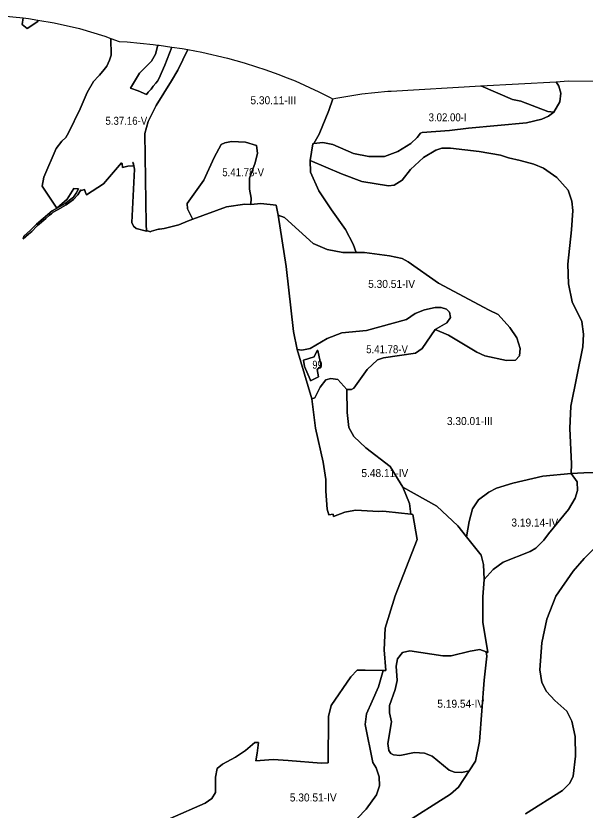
# Model space of a CAD drawing. Extents: x -591496 to -585489, y -1120610 to -1115685.
# Drawn here: x -589052 to -587628, y -1117681 to -1115696 of the extents above; entities that cross this region are included whole.
import ezdxf

# ---------------------------------------------------------------- set-up
doc = ezdxf.new("R2010")
doc.units = 0
doc.header["$LTSCALE"] = 8
doc.layers.add('40', color=7, linetype='Continuous', lineweight=25)
doc.layers.add('41', color=7, linetype='Continuous')

msp = doc.modelspace()

# ---------------------------------------------------------------- linework, layer by layer
at = {"layer": '40'}
for points in [[(-589085.427, -1115695.631), (-589033.025, -1115700.792), (-589035.5, -1115717.5), (-589023, -1115727.5), (-588997, -1115710), (-588996.427, -1115705.987), (-588955.74, -1115712.705), (-588892.011, -1115727.564), (-588829.39, -1115746.56), (-588813.95, -1115752.131), (-588813.5, -1115793.5), (-588817, -1115806), (-588823.97, -1115821.682), (-588830.41, -1115829.51), (-588842.09, -1115843.72), (-588844.5, -1115846.5), (-588857.5, -1115860), (-588873, -1115887), (-588890.503, -1115927.983), (-588920.25, -1115987.71), (-588926.285, -1115999.825), (-588926.5, -1116000), (-588937, -1116009), (-588950.5, -1116027), (-588982, -1116099), (-588985.5, -1116121.5), (-588949.5, -1116176), (-588923.5, -1116154), (-588906.817, -1116126.89), (-588894.56, -1116128.32), (-588900.38, -1116138.54), (-588907.74, -1116148.78), (-588910.49, -1116151.61), (-588928.5, -1116164.37), (-588941.5, -1116171.98), (-588960.88, -1116183.34), (-589000.12, -1116216.23), (-589015, -1116231.4), (-589031.8, -1116246.22), (-589032.98, -1116252.79), (-589020.34, -1116241.61), (-589012.05, -1116234.28), (-588999.48, -1116221.09), (-588997.78, -1116219.31), (-588976.73, -1116201.93), (-588967.37, -1116194.2), (-588962.57, -1116190.24), (-588959.07, -1116187.36), (-588958.15, -1116186.6), (-588938.64, -1116175.23), (-588937.13, -1116174.34), (-588925.78, -1116167.73), (-588907.39, -1116154.39), (-588896.85, -1116143.36), (-588891.47, -1116135), (-588888.661, -1116130.174), (-588887, -1116132.5), (-588880.305, -1116129.896), (-588877.56, -1116137.13), (-588875.1, -1116143.13), (-588832.19, -1116115.72), (-588787.477, -1116063.178), (-588786, -1116064.5), (-588785.405, -1116064.294), (-588784.46, -1116074.54), (-588771.67, -1116071.57), (-588756.88, -1116070.64), (-588758.78, -1116062.47), (-588758.357, -1116062.372), (-588754.5, -1116078.5), (-588761.5, -1116212.5), (-588757.5, -1116221.5), (-588751, -1116227), (-588725, -1116233.5), (-588721.219, -1116232.878), (-588715.72, -1116235.81), (-588712.16, -1116234.05), (-588700.61, -1116230.81), (-588694.53, -1116229.1), (-588692.58, -1116228.81), (-588680.32, -1116226.82), (-588643.83, -1116218.02), (-588622.31, -1116208.8), (-588609.21, -1116204.06), (-588524.463, -1116173.401), (-588479, -1116166.5), (-588464, -1116167), (-588438.5, -1116165), (-588400, -1116168.5), (-588395, -1116194), (-588375.5, -1116322.5), (-588357, -1116484.5), (-588348, -1116529.5), (-588311, -1116653), (-588302, -1116726), (-588283, -1116811.5), (-588276.5, -1116855), (-588276.5, -1116883.5)], [(-587579.5, -1116836.5), (-587630.5, -1116838), (-587662.5, -1116840), (-587662, -1116815.5), (-587665.5, -1116727), (-587663, -1116671.5), (-587633.5, -1116523), (-587631.5, -1116491.5), (-587636, -1116460), (-587660, -1116410.5), (-587669, -1116365.5), (-587670.5, -1116316), (-587662, -1116230.5), (-587658, -1116182.5), (-587660.5, -1116158.5), (-587670, -1116131.5), (-587698, -1116100), (-587732, -1116076.5), (-587755.5, -1116066), (-587790, -1116057.5), (-587819, -1116050.5), (-587839, -1116044), (-587892.5, -1116035), (-587964, -1116026), (-587986, -1116026), (-588001, -1116031.5), (-588032, -1116050), (-588064, -1116080), (-588085, -1116106), (-588105, -1116119), (-588119, -1116120.5), (-588186, -1116110), (-588237, -1116090.5), (-588315, -1116057.5), (-588308.5, -1116015.5), (-588306, -1116015), (-588283.5, -1116012), (-588258.5, -1116017), (-588207, -1116039.5), (-588168.5, -1116047.5), (-588129.5, -1116047.5), (-588096, -1116034.5), (-588063.5, -1116015), (-588047.5, -1116000), (-588039.5, -1115989), (-588035, -1115987.5), (-587967, -1115982.5), (-587919, -1115976.5), (-587774.5, -1115963), (-587736, -1115954), (-587719.5, -1115946.5), (-587705.5, -1115936.5), (-587691, -1115910.5), (-587688.5, -1115888.5), (-587693, -1115871.5), (-587699.742, -1115860.123), (-587669.707, -1115858.407), (-587547.277, -1115858.921)], [(-588085, -1117718), (-587964.5, -1117641.5), (-587944.5, -1117623.5), (-587918, -1117583), (-587902, -1117559), (-587892, -1117509.5), (-587880, -1117356.5), (-587873.5, -1117296.5), (-587875, -1117285.5), (-587871, -1117287), (-587883.5, -1117211), (-587883.5, -1117148), (-587880, -1117104.5), (-587857.5, -1117080), (-587832.5, -1117061), (-587765, -1117034.5), (-587751, -1117026), (-587730.5, -1117006), (-587719, -1116990.5), (-587669.5, -1116930), (-587652, -1116901), (-587646.5, -1116882), (-587647, -1116860.5), (-587662.5, -1116840), (-587630.5, -1116838), (-587579.5, -1116836.5)], [(-588276.5, -1116883.5), (-588273, -1116928.5), (-588269, -1116943), (-588257.783, -1116941.026), (-588257.78, -1116941.07), (-588257.29, -1116946.81), (-588228.999, -1116935.96), (-588206.5, -1116932), (-588200.967, -1116931.385), (-588144.53, -1116934.48), (-588134.232, -1116933.846), (-588125, -1116934.5), (-588063.5, -1116941), (-588061.589, -1116941.212), (-588058.91, -1116941.996), (-588047.5, -1117005), (-588102.5, -1117145.5), (-588127.5, -1117226.5), (-588130.5, -1117280.5), (-588126, -1117332.5), (-588132.5, -1117332.5), (-588177.5, -1117331), (-588197.5, -1117331), (-588214, -1117348), (-588262.5, -1117420), (-588269.5, -1117447), (-588270.5, -1117563), (-588288, -1117564), (-588370, -1117557.5), (-588407.5, -1117555), (-588451.5, -1117558), (-588448, -1117538.5), (-588445, -1117512.5), (-588454, -1117512), (-588477.5, -1117532.5), (-588502, -1117549), (-588535, -1117566), (-588548, -1117577), (-588552, -1117598.5), (-588552.5, -1117637.5), (-588561, -1117652.5), (-588578, -1117664), (-588666, -1117702.5)], [(-588218.5, -1117724), (-588175.5, -1117679), (-588149, -1117643), (-588142, -1117620.5), (-588142.5, -1117598), (-588150.5, -1117575.5), (-588159, -1117562), (-588178, -1117467.5), (-588174.5, -1117440.5), (-588160, -1117409), (-588144, -1117373), (-588132.5, -1117332.5), (-588126, -1117332.5), (-588130.5, -1117280.5), (-588127.5, -1117226.5), (-588102.5, -1117145.5), (-588047.5, -1117005), (-588058.91, -1116941.996), (-588061.589, -1116941.212), (-588063.5, -1116941), (-588066.5, -1116914.5), (-588083.5, -1116873.5), (-587998.5, -1116921), (-587946, -1116970.5), (-587924, -1116998)], [(-587777, -1117690.5), (-587684.5, -1117632), (-587666, -1117614), (-587657.5, -1117596), (-587651.5, -1117546.5), (-587652.5, -1117497), (-587660.5, -1117459), (-587673.5, -1117434), (-587703, -1117407), (-587724, -1117384.5), (-587735.5, -1117362), (-587740.5, -1117330.5), (-587735.5, -1117263), (-587723.5, -1117204), (-587701, -1117146), (-587657.5, -1117083.5), (-587629.5, -1117052.5), (-587552, -1116975.5)], [(-587552, -1116975.5), (-587629.5, -1117052.5), (-587657.5, -1117083.5), (-587701, -1117146), (-587723.5, -1117204), (-587735.5, -1117263), (-587740.5, -1117330.5), (-587735.5, -1117362), (-587724, -1117384.5), (-587703, -1117407), (-587673.5, -1117434), (-587660.5, -1117459), (-587652.5, -1117497), (-587651.5, -1117546.5), (-587657.5, -1117596), (-587666, -1117614), (-587684.5, -1117632), (-587777, -1117690.5)], [(-587924, -1116998), (-587887.5, -1117044), (-587881.5, -1117067), (-587880, -1117104.5), (-587883.5, -1117148), (-587883.5, -1117211), (-587871, -1117287), (-587875, -1117285.5), (-587891, -1117279.5), (-587915, -1117283.5), (-587962.5, -1117295.5), (-587983.5, -1117295.5), (-588066, -1117283), (-588084.5, -1117287.5), (-588097, -1117303), (-588100, -1117321), (-588098, -1117357), (-588103, -1117379.5), (-588117, -1117420), (-588116.5, -1117438), (-588111.5, -1117460.5), (-588121, -1117514.5), (-588118.5, -1117532.5), (-588113.5, -1117539.5), (-588107, -1117543), (-588091, -1117544.5), (-588054, -1117537), (-588029, -1117539), (-588010, -1117546.5), (-587968, -1117581), (-587954.5, -1117586.5), (-587936, -1117587.5), (-587918, -1117583), (-587944.5, -1117623.5), (-587964.5, -1117641.5), (-588085, -1117718)], [(-588666, -1117702.5), (-588578, -1117664), (-588561, -1117652.5), (-588552.5, -1117637.5), (-588552, -1117598.5), (-588548, -1117577), (-588535, -1117566), (-588502, -1117549), (-588477.5, -1117532.5), (-588454, -1117512), (-588445, -1117512.5), (-588448, -1117538.5), (-588451.5, -1117558), (-588407.5, -1117555), (-588370, -1117557.5), (-588288, -1117564), (-588270.5, -1117563), (-588269.5, -1117447), (-588262.5, -1117420), (-588214, -1117348), (-588197.5, -1117331), (-588177.5, -1117331), (-588132.5, -1117332.5), (-588144, -1117373), (-588160, -1117409), (-588174.5, -1117440.5), (-588178, -1117467.5), (-588159, -1117562), (-588150.5, -1117575.5), (-588142.5, -1117598), (-588142, -1117620.5), (-588149, -1117643), (-588175.5, -1117679), (-588218.5, -1117724)]]:
    msp.add_lwpolyline(points, dxfattribs=at)
for points in [[(-588997, -1115710), (-589023, -1115727.5), (-589035.5, -1115717.5), (-589033.025, -1115700.792), (-589020.304, -1115702.045), (-588996.427, -1115705.987)], [(-588745.52, -1115883.13), (-588724.53, -1115891.88), (-588720.22, -1115886.6), (-588713.53, -1115878.72), (-588707.84, -1115871.45), (-588701.53, -1115863.78), (-588697.583, -1115859.19), (-588693.731, -1115853.252), (-588678.873, -1115819.155), (-588661.07, -1115773.804), (-588635.894, -1115777.499), (-588621.728, -1115779.945), (-588646, -1115831), (-588662.5, -1115858), (-588701, -1115920), (-588721, -1115959.5), (-588729, -1115989.5), (-588725.5, -1116216), (-588725, -1116233.5), (-588751, -1116227), (-588757.5, -1116221.5), (-588761.5, -1116212.5), (-588754.5, -1116078.5), (-588758.357, -1116062.372), (-588758.78, -1116062.47), (-588756.88, -1116070.64), (-588771.67, -1116071.57), (-588784.46, -1116074.54), (-588785.405, -1116064.294), (-588786, -1116064.5), (-588787.477, -1116063.178), (-588832.19, -1116115.72), (-588875.1, -1116143.13), (-588877.56, -1116137.13), (-588880.305, -1116129.896), (-588887, -1116132.5), (-588888.661, -1116130.174), (-588891.47, -1116135), (-588896.85, -1116143.36), (-588907.39, -1116154.39), (-588925.78, -1116167.73), (-588937.13, -1116174.34), (-588938.64, -1116175.23), (-588958.15, -1116186.6), (-588959.07, -1116187.36), (-588962.57, -1116190.24), (-588967.37, -1116194.2), (-588976.73, -1116201.93), (-588997.78, -1116219.31), (-588999.48, -1116221.09), (-589012.05, -1116234.28), (-589020.34, -1116241.61), (-589032.98, -1116252.79), (-589031.8, -1116246.22), (-589015, -1116231.4), (-589000.12, -1116216.23), (-588960.88, -1116183.34), (-588941.5, -1116171.98), (-588928.5, -1116164.37), (-588910.49, -1116151.61), (-588907.74, -1116148.78), (-588900.38, -1116138.54), (-588894.56, -1116128.32), (-588906.817, -1116126.89), (-588923.5, -1116154), (-588949.5, -1116176), (-588985.5, -1116121.5), (-588982, -1116099), (-588950.5, -1116027), (-588937, -1116009), (-588926.5, -1116000), (-588926.285, -1115999.825), (-588920.25, -1115987.71), (-588890.503, -1115927.983), (-588873, -1115887), (-588857.5, -1115860), (-588844.5, -1115846.5), (-588842.09, -1115843.72), (-588830.41, -1115829.51), (-588823.97, -1115821.682), (-588817, -1115806), (-588813.5, -1115793.5), (-588813.95, -1115752.131), (-588793.58, -1115759.481), (-588773.137, -1115760.611), (-588708.014, -1115767.025), (-588696.61, -1115768.612), (-588702, -1115791), (-588712, -1115809), (-588742, -1115838.5), (-588764.428, -1115876.491)], [(-588720.22, -1115886.6), (-588724.53, -1115891.88), (-588745.52, -1115883.13), (-588764.428, -1115876.491), (-588742, -1115838.5), (-588712, -1115809), (-588702, -1115791), (-588696.61, -1115768.612), (-588693.334, -1115769.069), (-588661.07, -1115773.804), (-588678.873, -1115819.155), (-588693.731, -1115853.252), (-588697.583, -1115859.19), (-588701.53, -1115863.78), (-588707.84, -1115871.45), (-588713.53, -1115878.72)], [(-588258.512, -1115902.831), (-588269, -1115932), (-588292.5, -1115991), (-588306, -1116015), (-588308.5, -1116015.5), (-588315, -1116057.5), (-588314.5, -1116086), (-588293.5, -1116133), (-588262, -1116180.5), (-588227, -1116230), (-588208, -1116266), (-588200.5, -1116287), (-588233.5, -1116287.5), (-588273, -1116279.5), (-588308, -1116265), (-588379.5, -1116200), (-588395, -1116194), (-588400, -1116168.5), (-588438.5, -1116165), (-588464, -1116167), (-588463, -1116151), (-588467.5, -1116128.5), (-588467.5, -1116101.5), (-588453, -1116063), (-588447.5, -1116038.5), (-588449.5, -1116020), (-588477, -1116011), (-588512, -1116009.5), (-588529, -1116013), (-588538, -1116017), (-588555.5, -1116049.5), (-588581.5, -1116106), (-588623, -1116164.5), (-588622, -1116178), (-588610, -1116203), (-588609.981, -1116202.991), (-588609.21, -1116204.06), (-588622.31, -1116208.8), (-588643.83, -1116218.02), (-588680.32, -1116226.82), (-588692.58, -1116228.81), (-588694.53, -1116229.1), (-588700.61, -1116230.81), (-588712.16, -1116234.05), (-588715.72, -1116235.81), (-588721.219, -1116232.878), (-588725, -1116233.5), (-588725.5, -1116216), (-588729, -1115989.5), (-588721, -1115959.5), (-588701, -1115920), (-588662.5, -1115858), (-588646, -1115831), (-588621.728, -1115779.945), (-588586.01, -1115786.115), (-588522.281, -1115800.974), (-588480.632, -1115813.108), (-588449.682, -1115822.858), (-588428.711, -1115829.72), (-588393.583, -1115842.38), (-588379.303, -1115847.83), (-588353.187, -1115858.22), (-588293.581, -1115885.227), (-588265.44, -1115899.662), (-588259.225, -1115902.976)], [(-587705.5, -1115936.5), (-587719.5, -1115946.5), (-587736, -1115954), (-587774.5, -1115963), (-587919, -1115976.5), (-587967, -1115982.5), (-588035, -1115987.5), (-588039.5, -1115989), (-588047.5, -1116000), (-588063.5, -1116015), (-588096, -1116034.5), (-588129.5, -1116047.5), (-588168.5, -1116047.5), (-588207, -1116039.5), (-588258.5, -1116017), (-588283.5, -1116012), (-588306, -1116015), (-588292.5, -1115991), (-588269, -1115932), (-588258.512, -1115902.831), (-588251.05, -1115901.315), (-588186.486, -1115890.655), (-588121.363, -1115884.241), (-588112.987, -1115883.727), (-587888.26, -1115870.891), (-587809.5, -1115904.5), (-587788, -1115909), (-587721, -1115934.5)], [(-587691, -1115910.5), (-587705.5, -1115936.5), (-587721, -1115934.5), (-587788, -1115909), (-587809.5, -1115904.5), (-587888.26, -1115870.891), (-587699.742, -1115860.123), (-587693, -1115871.5), (-587688.5, -1115888.5)], [(-588464, -1116167), (-588479, -1116166.5), (-588524.463, -1116173.401), (-588609.21, -1116204.06), (-588609.981, -1116202.991), (-588610, -1116203), (-588622, -1116178), (-588623, -1116164.5), (-588581.5, -1116106), (-588555.5, -1116049.5), (-588538, -1116017), (-588529, -1116013), (-588512, -1116009.5), (-588477, -1116011), (-588449.5, -1116020), (-588447.5, -1116038.5), (-588453, -1116063), (-588467.5, -1116101.5), (-588467.5, -1116128.5), (-588463, -1116151)], [(-587662.5, -1116840), (-587733.5, -1116846), (-587808, -1116863.5), (-587849, -1116876.5), (-587868.5, -1116886), (-587894, -1116905.5), (-587909, -1116928), (-587918, -1116959.5), (-587924, -1116998), (-587946, -1116970.5), (-587998.5, -1116921), (-588083.5, -1116873.5), (-588097, -1116852), (-588115, -1116822.5), (-588176, -1116775.5), (-588206, -1116747.5), (-588218.5, -1116725), (-588222.5, -1116687), (-588224, -1116630), (-588212, -1116630), (-588206, -1116626), (-588173, -1116579.5), (-588146.5, -1116555.5), (-588131.5, -1116550.5), (-588052, -1116538.5), (-588035, -1116527.5), (-588002.5, -1116480), (-587969, -1116494), (-587898.5, -1116536.5), (-587878, -1116545.5), (-587824.5, -1116557.5), (-587802, -1116556.5), (-587792, -1116545.5), (-587790, -1116527.5), (-587798, -1116500.5), (-587815.5, -1116475), (-587845, -1116442.5), (-587867.5, -1116431), (-587994, -1116363.5), (-588070.5, -1116310.5), (-588085, -1116302.5), (-588116.5, -1116295.5), (-588179.5, -1116287), (-588200.5, -1116287), (-588208, -1116266), (-588227, -1116230), (-588262, -1116180.5), (-588293.5, -1116133), (-588314.5, -1116086), (-588315, -1116057.5), (-588237, -1116090.5), (-588186, -1116110), (-588119, -1116120.5), (-588105, -1116119), (-588085, -1116106), (-588064, -1116080), (-588032, -1116050), (-588001, -1116031.5), (-587986, -1116026), (-587964, -1116026), (-587892.5, -1116035), (-587839, -1116044), (-587819, -1116050.5), (-587790, -1116057.5), (-587755.5, -1116066), (-587732, -1116076.5), (-587698, -1116100), (-587670, -1116131.5), (-587660.5, -1116158.5), (-587658, -1116182.5), (-587662, -1116230.5), (-587670.5, -1116316), (-587669, -1116365.5), (-587660, -1116410.5), (-587636, -1116460), (-587631.5, -1116491.5), (-587633.5, -1116523), (-587663, -1116671.5), (-587665.5, -1116727), (-587662, -1116815.5)], [(-588200.5, -1116287), (-588179.5, -1116287), (-588116.5, -1116295.5), (-588085, -1116302.5), (-588070.5, -1116310.5), (-587994, -1116363.5), (-587867.5, -1116431), (-587845, -1116442.5), (-587815.5, -1116475), (-587798, -1116500.5), (-587790, -1116527.5), (-587792, -1116545.5), (-587802, -1116556.5), (-587824.5, -1116557.5), (-587878, -1116545.5), (-587898.5, -1116536.5), (-587969, -1116494), (-588002.5, -1116480), (-587973.5, -1116463), (-587964, -1116449.5), (-587966.5, -1116436.5), (-587974, -1116429), (-587988, -1116425), (-588002.5, -1116425), (-588029.5, -1116430.5), (-588052.5, -1116439.5), (-588074, -1116455), (-588174.5, -1116482), (-588236, -1116488), (-588273, -1116502), (-588315, -1116527), (-588336, -1116531), (-588348, -1116529.5), (-588357, -1116484.5), (-588375.5, -1116322.5), (-588395, -1116194), (-588379.5, -1116200), (-588308, -1116265), (-588273, -1116279.5), (-588233.5, -1116287.5)], [(-588002.5, -1116480), (-588035, -1116527.5), (-588052, -1116538.5), (-588131.5, -1116550.5), (-588146.5, -1116555.5), (-588173, -1116579.5), (-588206, -1116626), (-588212, -1116630), (-588224, -1116630), (-588246, -1116605), (-588264, -1116602.5), (-588276.5, -1116605.5), (-588290.5, -1116624), (-588303.5, -1116650.5), (-588311, -1116653), (-588348, -1116529.5), (-588336, -1116531), (-588315, -1116527), (-588273, -1116502), (-588236, -1116488), (-588174.5, -1116482), (-588074, -1116455), (-588052.5, -1116439.5), (-588029.5, -1116430.5), (-588002.5, -1116425), (-587988, -1116425), (-587974, -1116429), (-587966.5, -1116436.5), (-587964, -1116449.5), (-587973.5, -1116463)], [(-588294.5, -1116598), (-588314.279, -1116607.889), (-588315.63, -1116604.29), (-588329.15, -1116572.2), (-588331.762, -1116556.451), (-588305, -1116548), (-588297.884, -1116531.989), (-588297.1, -1116531.88), (-588296.554, -1116532.031), (-588288, -1116571), (-588298, -1116580)], [(-588294.5, -1116598), (-588298, -1116580), (-588288, -1116571), (-588296.554, -1116532.031), (-588297.1, -1116531.88), (-588297.884, -1116531.989), (-588305, -1116548), (-588331.762, -1116556.451), (-588329.15, -1116572.2), (-588315.63, -1116604.29), (-588314.279, -1116607.889)], [(-588224, -1116630), (-588222.5, -1116687), (-588218.5, -1116725), (-588206, -1116747.5), (-588176, -1116775.5), (-588115, -1116822.5), (-588097, -1116852), (-588083.5, -1116873.5), (-588066.5, -1116914.5), (-588063.5, -1116941), (-588125, -1116934.5), (-588134.232, -1116933.846), (-588144.53, -1116934.48), (-588200.967, -1116931.385), (-588206.5, -1116932), (-588228.999, -1116935.96), (-588257.29, -1116946.81), (-588257.78, -1116941.07), (-588257.783, -1116941.026), (-588269, -1116943), (-588273, -1116928.5), (-588276.5, -1116883.5), (-588276.5, -1116855), (-588283, -1116811.5), (-588302, -1116726), (-588311, -1116653), (-588303.5, -1116650.5), (-588290.5, -1116624), (-588276.5, -1116605.5), (-588264, -1116602.5), (-588246, -1116605)], [(-587880, -1117104.5), (-587881.5, -1117067), (-587887.5, -1117044), (-587924, -1116998), (-587918, -1116959.5), (-587909, -1116928), (-587894, -1116905.5), (-587868.5, -1116886), (-587849, -1116876.5), (-587808, -1116863.5), (-587733.5, -1116846), (-587662.5, -1116840), (-587647, -1116860.5), (-587646.5, -1116882), (-587652, -1116901), (-587669.5, -1116930), (-587719, -1116990.5), (-587730.5, -1117006), (-587751, -1117026), (-587765, -1117034.5), (-587832.5, -1117061), (-587857.5, -1117080)], [(-587875, -1117285.5), (-587873.5, -1117296.5), (-587880, -1117356.5), (-587892, -1117509.5), (-587902, -1117559), (-587918, -1117583), (-587936, -1117587.5), (-587954.5, -1117586.5), (-587968, -1117581), (-588010, -1117546.5), (-588029, -1117539), (-588054, -1117537), (-588091, -1117544.5), (-588107, -1117543), (-588113.5, -1117539.5), (-588118.5, -1117532.5), (-588121, -1117514.5), (-588111.5, -1117460.5), (-588116.5, -1117438), (-588117, -1117420), (-588103, -1117379.5), (-588098, -1117357), (-588100, -1117321), (-588097, -1117303), (-588084.5, -1117287.5), (-588066, -1117283), (-587983.5, -1117295.5), (-587962.5, -1117295.5), (-587915, -1117283.5), (-587891, -1117279.5)]]:
    msp.add_lwpolyline(points, close=True, dxfattribs=at)

# ---------------------------------------------------------------- texts
at = {"layer": '41'}
for s, width, p in [('5.30.11-III', 0.95, (-588464.75, -1115916.563)), ('5.37.16-V', 0.9, (-588827.375, -1115967.875)), ('3.02.00-I', 0.9, (-588019.031, -1115959.25)), ('5.41.78-V', 0.9, (-588535.25, -1116096.5)), ('5.30.51-IV', 0.95, (-588170.25, -1116375.75)), ('5.41.78-V', 0.9, (-588175.156, -1116539)), ('99', 0.85, (-588309.875, -1116577.625)), ('3.30.01-III', 0.95, (-587973.25, -1116718.5)), ('5.48.11-IV', 0.95, (-588187.25, -1116848.563)), ('3.19.14-IV', 0.95, (-587812.031, -1116972.25)), ('5.19.54-IV', 0.95, (-587997.25, -1117425.188)), ('5.30.51-IV', 0.95, (-588366.25, -1117659.5))]:
    msp.add_text(s, height=20, dxfattribs=dict(at, width=width)).set_placement(p)

doc.saveas('drawing.dxf')
